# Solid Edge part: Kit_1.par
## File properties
Dokumentum tartalom típus: 0
Last saved by: ahadarics
Revision: 76
Sűrűség: 0,000 kg/m^3
Pontosság: 0,990
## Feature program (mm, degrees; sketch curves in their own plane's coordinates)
base feature "unnamed BaseFeature 1"
sketch for "unnamed Hole 1" plane through (-19, -19, 90) normal (0, 0, 1) x-axis (0, 1, 0)
  hole centre (0, 0) bore radius 2.4585
hole "unnamed Hole 1" through
sketch for "unnamed Hole 2" plane through (-19, -19, 90) normal (0, 0, 1) x-axis (0, 1, 0)
  hole centre (38, 0) bore radius 2.4585
hole "unnamed Hole 2" through
sketch for "unnamed Hole 3" plane through (-19, -19, 90) normal (0, 0, 1) x-axis (0, 1, 0)
  hole centre (38, -38) bore radius 2.4585
hole "unnamed Hole 3" through
sketch for "unnamed Hole 4" plane through (-19, -19, 90) normal (0, 0, 1) x-axis (0, 1, 0)
  hole centre (0, -38) bore radius 2.4585
hole "unnamed Hole 4" through
pattern "unnamed Pattern 1" of "unnamed Hole 1", "unnamed Hole 2", "unnamed Hole 3", "unnamed Hole 4"
sketch for "Furat_5" plane through (-27.3367, 0, 87.75) normal (-0.999962, 0, 0.008727) x-axis (0, 1, 0)
  hole centre (-0.0001, 0.7497) bore radius 4.283
hole "Furat_5" diameter 8.566 finite
thread "unnamed Thread 1"
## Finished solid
Body 1: solid body, 305 faces, 714 edges, 430 vertices, 4 internal voids.
  Faces by surface: plane 147, cylinder 74, swept 43, torus 22, cone 18, spline 1
  Edges by curve: line 415, circle 174, spline 102, ellipse 12, curve on surface 11
Bounding box of the edges (mm; curved faces can reach further): 54.800 x 54.800 x 14.500, from (-27.4, -27.4, 80.5) to (27.4, 27.4, 95).
Cylindrical faces by radius (mm): R0.2 x36, R0.519 x1, R2.4585 x4, R2.5402 x12, R2.6 x4, R3.75 x4, R3.85 x4, R4.283 x1, R4.5 x4, R6.27 x1, R6.85 x1, R7 x1, R8.25 x1
Conical faces (half-angle, radius in mm at the cone's reference point): 0.5 deg R6.75 x4, 7 deg R7.5925 x1, 14 deg R6.135 x1, 14 deg R6.4811 x1, 17 deg R6.135 x1, 23 deg R6.829 x1, 42.5 deg R6.1233 x1, 45 deg R2.7085 x4, 45 deg R7 x1, 84 deg R6.4608 x1, 85 deg R7.9463 x1, 87 deg R6.1765 x1
Toroidal faces (ring radius, tube radius in mm): R2.9402 r0.4 x12, R3.55 r0.2 x8, R6.8057 r0.2025 x1, R7.2522 r0.2925 x1
Planar faces by outward normal: +x 13, +y 14, +z 24, -x 14, -y 15, -z 1, oblique 66
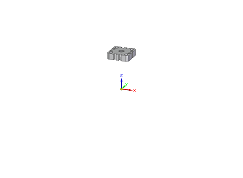
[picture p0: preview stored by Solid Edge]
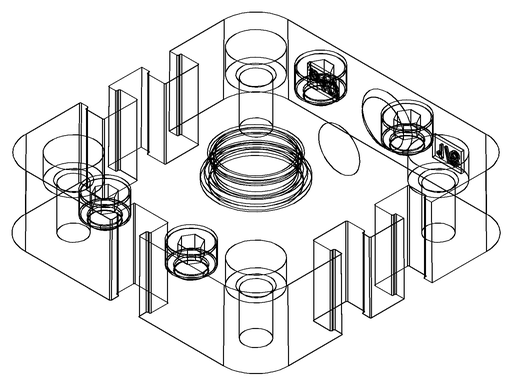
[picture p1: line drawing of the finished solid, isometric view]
